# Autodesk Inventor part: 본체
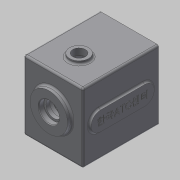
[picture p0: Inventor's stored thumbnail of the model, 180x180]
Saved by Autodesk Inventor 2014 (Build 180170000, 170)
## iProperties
Created: 2016-02
Part Number: 본체
Material: 일반
Document SubType Name: Modeling
Designer: mduedu
Density: 2.71 g/cm^3
Appearance: Default
Author: mduedu
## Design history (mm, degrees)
sketch "스케치1"
  geometry: L1 (-47, -47)-(47, -47); L2 (47, -47)-(47, 63); L3 (47, 63)-(-47, 63); L4 (-47, 63)-(-47, -47); 2 further points
  constraints: 8 end point, 2 parallel, 1 horizontal, 1 midpoint, 1 perpendicular, 1 vertical alignment
  dimensions: "d0" = 94 distance of L2.end L3.end; "d155" = 110 distance of L1.end L2.end; "d156" = 47 distance from line of L1 point (0, 0)
extrude "돌출1" new body sketch "스케치1" distance "d2" = 120; taper "d3" = 0 deg
sketch "스케치3"
  geometry: L1 (47, -47)-(-47, -47) reference; L2 (47, 63)-(47, -47) reference; L3 (-47, 63)-(47, 63) reference; L4 (-47, -47)-(-47, 63) reference; L5 (37, 53)-(37, -37); L6 (37, -37)-(-37, -37); L7 (-37, -37)-(-37, 53); L8 (-37, 53)-(37, 53); 1 further point
  constraints: 8 end point, 3 other
  dimensions: "d226" = 10 distance between parallel lines of L8 L3
extrude "돌출3" cut sketch "스케치3" distance "d11" = 110; taper "d12" = 0 deg
sketch "스케치4"
  geometry: C1 r 21 at (0, 11); 1 further point
  constraints: 1 centre point, 1 vertical alignment
  dimensions: "d13" = 21 radius of C1; "d227" = 11 distance of point (0, 0) C1.centre
extrude "돌출4" join sketch "스케치4" distance "d16" = 7; taper "d17" = 0 deg
sketch "스케치5"
  geometry: C1 r 15 at (0, -20); 1 further point
  constraints: 1 centre point, 1 vertical alignment
  dimensions: "d18" = 15 radius of C1; "d20" = 20 distance of point (0, 0) C1.centre
extrude "돌출5" join sketch "스케치5" distance "d21" = 7; taper "d22" = 0 deg
sketch "스케치6"
  geometry: C1 r 30 at (0, 11); A1 r 21 centre (0, 11) between (8.978, -7.984) and (-8.978, -7.984) reference; 1 further point
  constraints: 1 centre point, 1 coincident
  dimensions: "d228" = 60 diameter of C1
extrude "돌출6" join sketch "스케치6" distance "d25" = 7; taper "d26" = -3 deg
hole "구멍1" diameter "d29" = 35; stored, may be unused: countersink angle "d33" = 90 deg, drill point angle "d35" = 0 deg; dims "d27" = 10, "d28" = 10, "d30" = 6, "d31" = 4, "d32" = 2, "d34" = 10
hole "구멍2" diameter "d38" = 22; stored, may be unused: countersink angle "d42" = 90 deg, drill point angle "d44" = 0 deg; dims "d36" = 10, "d37" = 10, "d39" = 6, "d40" = 4, "d41" = 2, "d43" = 7
hole "구멍3" diameter "d47" = 19; stored, may be unused: countersink angle "d51" = 90 deg, drill point angle "d53" = 0 deg; dims "d45" = 10, "d46" = 10, "d48" = 6, "d49" = 4, "d50" = 2, "d52" = 1
hole "구멍4" diameter "d56" = 32; stored, may be unused: countersink angle "d60" = 90 deg, drill point angle "d62" = 0 deg; dims "d57" = 6, "d58" = 4, "d59" = 2, "d61" = 8, "d220" = 10, "d221" = 10
hole "구멍5" diameter "d65" = 25; stored, may be unused: countersink angle "d69" = 90 deg, drill point angle "d71" = 0 deg; dims "d63" = 10, "d64" = 10, "d66" = 6, "d67" = 4, "d68" = 2, "d70" = 8
fillet "모깎기2" dims "d73" = 0.3
fillet "모깎기3" dims "d74" = 2
chamfer "모따기1" distance "d75" = 1; stored, may be unused: second distance "d76" = 2, angle "d77" = 45 deg
fillet "모깎기4" dims "d78" = 3
fillet "모깎기23" dims "d240" = 1
fillet "모깎기20" dims "d229" = 3
sketch "스케치23"
  geometry: L1 (-37, 53)-(37, 53) reference; L2 (37, 53)-(37, -37) reference; L3 (37, -37)-(-37, -37) reference; L4 (-37, -37)-(-37, 53) reference; L5 (44, -47)-(-44, -47) reference; L6 (47, 60)-(47, -44) reference; L7 (-44, 63)-(44, 63) reference; L8 (-47, -44)-(-47, 60) reference; C1 r 10 at (-37, 53); C2 r 10 at (37, 53); C3 r 10 at (-37, -37); C4 r 10 at (37, -37); A1 r 3 centre (-44, -44) between (-47, -44) and (-44, -47) reference; A2 r 3 centre (44, -44) between (44, -47) and (47, -44) reference; A3 r 3 centre (44, 60) between (47, 60) and (44, 63) reference; A4 r 3 centre (-44, 60) between (-44, 63) and (-47, 60) reference; 1 further point
  constraints: 4 centre point, 4 coincident, 3 equal radius
  dimensions: "d230" = 20 diameter of C1
extrude "돌출22" join sketch "스케치23" stored distance "d235" = 10; taper "d236" = 0 deg
fillet "모깎기21" dims "d237" = 3
node "작업 평면1"
fillet "모깎기22" dims "d239" = 1
sketch "스케치12"
  geometry: A1 r 10 centre (-37, 53) between (-34.692, 43.27) and (-27.27, 50.692) reference; A2 r 10 centre (37, 53) between (27.27, 50.692) and (34.692, 43.27) reference; A3 r 10 centre (37, -37) between (34.692, -27.27) and (27.27, -34.692) reference; A4 r 10 centre (-37, -37) between (-27.27, -34.692) and (-34.692, -27.27) reference; 5 further points
  constraints: 4 coincident
hole "구멍6" sketch "스케치12" at (-37, 53), (37, 53), (37, -37), (-37, -37) diameter "d122" = 3.242; stored, may be unused: countersink angle "d126" = 90 deg, drill point angle "d128" = 120 deg; dims "d123" = 7, "d124" = 4, "d125" = 2, "d127" = 9
sketch "스케치20"
  geometry: L1 (44, 0)-(-44, 0) reference; L2 (44, -120)-(-44, -120) reference; L3 (0, 0)-(0, -120); L4 (-44, -120)-(-44, 0) reference; L5 (44, 0)-(44, -120) reference; C1 r 10 at (0, -79)
  constraints: 2 end point, 1 centre point, 1 midpoint, 1 point on line
  dimensions: "d189" = 20 diameter of C1; "d190" = 41 distance from line of C1.centre L2
extrude "돌출19" cut sketch "스케치20" stored distance "d191" = 10; taper "d192" = 0 deg
sketch "스케치18"
  geometry: C1 r 15 at (0, -79); C2 r 10 at (0, -79) reference; 1 further point
  constraints: 1 centre point, 1 concentric
  dimensions: "d174" = 30 diameter of C1
extrude "돌출17" join sketch "스케치18" distance "d175" = 5; taper "d176" = 0 deg
fillet "모깎기16" dims "d177" = 3
sketch "스케치19"
  geometry: C1 r 15 at (24.351, 79); C2 r 10 at (24.351, 79) reference; 1 further point
  constraints: 1 centre point, 1 concentric
  dimensions: "d178" = 30 diameter of C1
extrude "돌출18" cut sketch "스케치19" distance "d181" = 5; taper "d182" = 0 deg
chamfer "모따기5" distance "d183" = 1; stored, may be unused: second distance "d184" = 2, angle "d185" = 45 deg
fillet "모깎기24" dims "d242" = 3, "d243" = 3
sketch "스케치24"
  geometry: L1 (-95, 67)-(-25, 67); L2 (-25, 67)-(-25, 37); L3 (-25, 37)-(-95, 37); L4 (-95, 37)-(-95, 67); L5 (0, 0)-(0, 104) reference; L6 (-95, 52)-(-25, 52); L7 (-60, 67)-(-60, 37); A1 r 15 centre (-95, 52) between (-95, 37) and (-95, 67); A2 r 15 centre (-25, 52) between (-25, 67) and (-25, 37); A3 r 15 centre (-25, 52) between (-25, 37) and (-25, 67); A4 r 15 centre (-95, 52) between (-95, 67) and (-95, 37); 2 further points
  constraints: 12 end point, 8 point on circle, 5 midpoint, 4 centre point, 2 parallel, 2 perpendicular, 1 horizontal, 1 horizontal alignment
  dimensions: "d244" = 60 distance between parallel lines of L7 L5; "d245" = 100 dimension on A2 A1; "d246" = 30 distance between parallel lines of L3 L1
extrude "돌출23" join sketch "스케치24" distance "d247" = 3; taper "d248" = 0 deg
fillet "모깎기25" dims "d249" = 3
sketch "스케치25"
  geometry: L1 (-25, 67)-(-95, 67) reference; L2 (-95, 37)-(-25, 37) reference; A1 r 15 centre (-95, 52) between (-95, 67) and (-95, 37) reference; A2 r 15 centre (-25, 52) between (-25, 37) and (-25, 67) reference; 3 further points
  constraints: 1 horizontal alignment, 1 midpoint, 1 vertical alignment, 1 other
feature "엠보싱3" sketch "스케치25" dims "d250" = 0.5, "d251" = 0
sketch "스케치26"
  geometry: L1 (14.367, 127)-(73.633, 127) reference; L2 (0, 0)-(88, 0) reference; L3 (88, 120)-(0, 120) reference; 5 further points
  constraints: 3 vertical alignment, 2 midpoint
  dimensions: "d252" = 35 distance from line of point (44, 35) L2; "d253" = 35 distance from line of point (44, 85) L3; "d254" = 50 distance of point (44, 35) point (44, 85) (derived)
hole "구멍8" sketch "스케치26" at (44, 85), (44, 35) diameter "d255" = 6.647; stored, may be unused: countersink angle "d259" = 90 deg, drill point angle "d261" = 118 deg; dims "d256" = 6, "d257" = 4, "d258" = 2, "d260" = 8
node "솔리드1"
node "투영된 루프1"
node "투영된 루프4"
node "투영된 루프5"
node "투영된 루프6"
